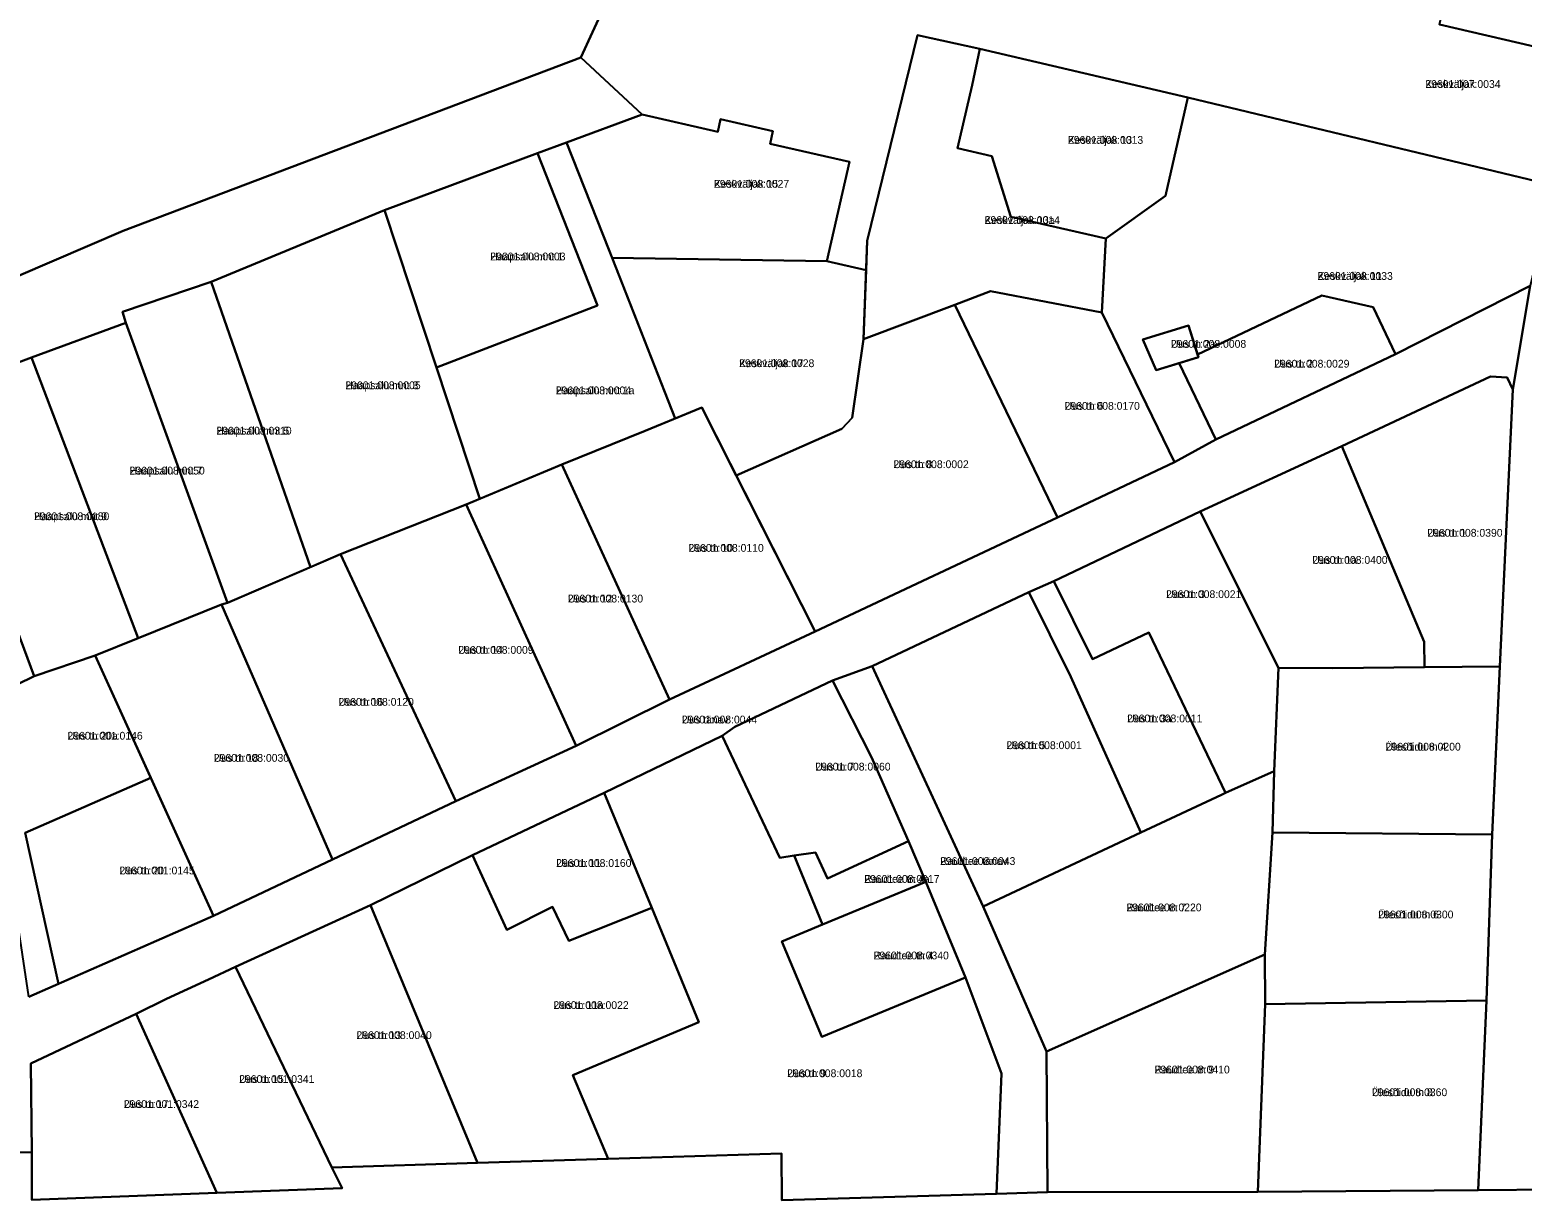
# Model space of a CAD drawing. Extents: x 518839 to 525192, y 6573164 to 6576561.
# Drawn here: x 523942.5 to 524230.2, y 6574325 to 6574550.6 of the extents above; entities that cross this region are included whole.
import ezdxf

# ---------------------------------------------------------------- set-up
doc = ezdxf.new("R2010")
doc.units = 0
for name, color, linetype in [('L_AADRESS', 7, 'Continuous'), ('PIIR', 7, 'Continuous'), ('TUNNUS', 7, 'Continuous')]:
    doc.layers.add(name, color=color, linetype=linetype)

msp = doc.modelspace()

# ---------------------------------------------------------------- linework, layer by layer
at = {"layer": 'PIIR'}
for points in [[(524261.43, 6574568.93), (524244.4, 6574544.59), (524214.28, 6574551.57), (524221.35, 6574582.67)], [(524113.63, 6574549.55), (524125.65, 6574546.87), (524124.21, 6574539.9), (524121.37, 6574527.77), (524127.96, 6574526.22), (524131.65, 6574514.49), (524149.94, 6574510.31), (524149.18, 6574496.1), (524127.7, 6574500.17), (524120.82, 6574497.56), (524103.22, 6574490.94), (524103.93, 6574509.88)], [(524125.65, 6574546.87), (524165.75, 6574537.51), (524161.44, 6574518.56), (524149.94, 6574510.31), (524131.65, 6574514.49), (524127.96, 6574526.22), (524121.37, 6574527.77), (524124.21, 6574539.9)], [(524165.75, 6574537.51), (524236.37, 6574520.54), (524231.72, 6574501.21), (524205.78, 6574488.03), (524201.49, 6574497.08), (524191.56, 6574499.32), (524167.64, 6574487.97), (524165.87, 6574493.59), (524157.06, 6574490.89), (524159.65, 6574484.94), (524164.05, 6574486.32), (524171.13, 6574471.57), (524163.19, 6574467.21), (524149.18, 6574496.1), (524149.94, 6574510.31), (524161.44, 6574518.56)], [(524046.01, 6574528.85), (524060.59, 6574534.25), (524075.12, 6574530.92), (524075.68, 6574533.35), (524085.77, 6574531.04), (524085.21, 6574528.6), (524100.5, 6574525.1), (524096.14, 6574505.98), (524054.77, 6574506.58), (524054.13, 6574508.2)], [(524046.01, 6574528.85), (524054.13, 6574508.2), (524066.94, 6574475.63), (524061.16, 6574473.29), (524045.1, 6574466.79), (524029.26, 6574460.17), (524020.9, 6574485.49), (524051.93, 6574497.39), (524040.38, 6574526.76)], [(524040.38, 6574526.76), (524051.93, 6574497.39), (524020.9, 6574485.49), (524010.89, 6574515.83)], [(524010.89, 6574515.83), (524020.9, 6574485.49), (524029.26, 6574460.17), (524026.62, 6574459.07), (524002.42, 6574449.49), (523996.62, 6574446.97), (523977.46, 6574501.97)], [(524054.77, 6574506.58), (524096.14, 6574505.98), (524103.72, 6574504.25), (524103.22, 6574490.94), (524101.04, 6574475.74), (524099.06, 6574473.65), (524078.71, 6574464.62), (524072.05, 6574477.78), (524066.94, 6574475.63)], [(523996.62, 6574446.97), (523980.65, 6574440.13), (523961.02, 6574494.08), (523960.36, 6574496.17), (523977.46, 6574501.97)], [(524127.7, 6574500.17), (524149.18, 6574496.1), (524163.19, 6574467.21), (524140.64, 6574456.54), (524120.82, 6574497.56)], [(524140.64, 6574456.54), (524093.9, 6574434.59), (524078.71, 6574464.62), (524099.06, 6574473.65), (524101.04, 6574475.74), (524103.22, 6574490.94), (524120.82, 6574497.56)], [(524164.05, 6574486.32), (524167.79, 6574487.49), (524167.64, 6574487.97), (524191.56, 6574499.32), (524201.49, 6574497.08), (524205.78, 6574488.03), (524171.13, 6574471.57)], [(523963.4, 6574433.26), (523942.85, 6574487.39), (523961.02, 6574494.08), (523980.65, 6574440.13), (523979.48, 6574439.76)], [(524167.79, 6574487.49), (524159.65, 6574484.94), (524157.06, 6574490.89), (524165.87, 6574493.59)], [(523923.27, 6574480.06), (523942.85, 6574487.39), (523963.4, 6574433.26), (523955.11, 6574429.92), (523943.34, 6574425.96)], [(524224.11, 6574483.71), (524227.33, 6574483.53), (524228.42, 6574481.2), (524225.88, 6574427.83), (524211.35, 6574427.68), (524211.3, 6574432.57), (524195.42, 6574470.32)], [(523923.27, 6574480.06), (523943.34, 6574425.96), (523933.73, 6574421.28), (523927.24, 6574420.14), (523906.23, 6574473.68)], [(524045.1, 6574466.79), (524061.16, 6574473.29), (524072.05, 6574477.78), (524093.9, 6574434.59), (524065.86, 6574421.45)], [(524211.3, 6574432.57), (524211.35, 6574427.68), (524193.71, 6574427.5), (524183.2, 6574427.59), (524168.15, 6574457.71), (524195.42, 6574470.32)], [(524045.1, 6574466.79), (524065.86, 6574421.45), (524047.84, 6574412.54), (524026.62, 6574459.07)], [(524026.62, 6574459.07), (524047.84, 6574412.54), (524024.62, 6574401.85), (524002.42, 6574449.49)], [(524139.92, 6574444.3), (524168.15, 6574457.71), (524183.2, 6574427.59), (524182.42, 6574407.66), (524173.02, 6574403.45), (524158.24, 6574434.41), (524147.4, 6574429.26)], [(523979.48, 6574439.76), (523980.65, 6574440.13), (524002.42, 6574449.49), (524024.62, 6574401.85), (524000.89, 6574390.65)], [(524104.91, 6574427.9), (524135.07, 6574442.17), (524143.18, 6574425.84), (524156.7, 6574395.81), (524126.31, 6574381.54)], [(524135.07, 6574442.17), (524139.92, 6574444.3), (524147.4, 6574429.26), (524158.24, 6574434.41), (524173.02, 6574403.45), (524172.27, 6574403.11), (524156.7, 6574395.81), (524143.18, 6574425.84)], [(523955.11, 6574429.92), (523963.4, 6574433.26), (523979.48, 6574439.76), (524000.89, 6574390.65), (523977.96, 6574379.73)], [(523942.36, 6574364.13), (523933.73, 6574421.28), (523943.34, 6574425.96), (523955.11, 6574429.92), (523965.83, 6574406.37), (523941.65, 6574395.76), (523948.05, 6574366.62)], [(524097.28, 6574425.15), (524104.91, 6574427.9), (524126.31, 6574381.54), (524138.49, 6574353.61), (524138.73, 6574326.48), (524128.88, 6574326.17), (524129.82, 6574349.36), (524122.87, 6574367.85), (524115.23, 6574386.33), (524111.93, 6574394.17), (524104.76, 6574410.33)], [(524182.42, 6574407.66), (524183.2, 6574427.59), (524193.71, 6574427.5), (524211.35, 6574427.68), (524225.88, 6574427.83), (524224.41, 6574395.41), (524182.05, 6574395.81)], [(524078.45, 6574416.17), (524097.28, 6574425.15), (524104.76, 6574410.33), (524111.93, 6574394.17), (524096.32, 6574386.94), (524094, 6574391.99), (524089.86, 6574391.37), (524087.08, 6574390.92), (524075.96, 6574414.43)], [(524062.4, 6574381.3), (524053.25, 6574403.45), (524075.96, 6574414.43), (524087.08, 6574390.92), (524089.86, 6574391.37), (524095.33, 6574378.08), (524087.48, 6574374.84), (524095.21, 6574356.41), (524122.87, 6574367.85), (524129.82, 6574349.36), (524128.88, 6574326.17), (524087.52, 6574324.95), (524087.42, 6574333.93), (524053.99, 6574332.93), (524047.23, 6574349.06), (524071.46, 6574359.29)], [(524138.49, 6574353.61), (524126.31, 6574381.54), (524156.7, 6574395.81), (524172.27, 6574403.11), (524173.02, 6574403.45), (524182.42, 6574407.66), (524182.05, 6574395.81), (524180.58, 6574372.29)], [(523948.05, 6574366.62), (523941.65, 6574395.76), (523965.83, 6574406.37), (523977.96, 6574379.73)], [(524053.25, 6574403.45), (524062.4, 6574381.3), (524046.41, 6574374.93), (524043.25, 6574381.47), (524034.5, 6574377.05), (524027.83, 6574391.43)], [(524223.35, 6574363.46), (524180.64, 6574362.74), (524180.58, 6574372.29), (524182.05, 6574395.81), (524224.41, 6574395.41)], [(524089.86, 6574391.37), (524094, 6574391.99), (524096.32, 6574386.94), (524111.93, 6574394.17), (524115.23, 6574386.33), (524095.33, 6574378.08)], [(524008.18, 6574381.82), (524027.83, 6574391.43), (524034.5, 6574377.05), (524043.25, 6574381.47), (524046.41, 6574374.93), (524062.4, 6574381.3), (524071.46, 6574359.29), (524047.23, 6574349.06), (524053.99, 6574332.93), (524028.8, 6574332.17)], [(524122.87, 6574367.85), (524095.21, 6574356.41), (524087.48, 6574374.84), (524095.33, 6574378.08), (524115.23, 6574386.33)], [(523982.2, 6574369.96), (524008.18, 6574381.82), (524028.8, 6574332.17), (524000.72, 6574331.27)], [(523978.59, 6574326.39), (523963.04, 6574360.87), (523968.9, 6574363.77), (523976.95, 6574367.51), (523982.2, 6574369.96), (524000.72, 6574331.27), (524002.73, 6574327.27)], [(524138.49, 6574353.61), (524180.58, 6574372.29), (524180.64, 6574362.74), (524179.26, 6574326.53), (524138.73, 6574326.48)], [(524179.26, 6574326.53), (524180.64, 6574362.74), (524223.35, 6574363.46), (524221.73, 6574326.86)], [(523942.7, 6574351.27), (523963.04, 6574360.87), (523978.59, 6574326.39), (523942.94, 6574325.03), (523942.9, 6574334.18)]]:
    msp.add_lwpolyline(points, close=True, dxfattribs=at)
for points in [[(524055.5, 6574559.93), (524048.74, 6574545.24), (523960.55, 6574511.82), (523926.54, 6574497.21), (523925.89, 6574498.49), (523851.65, 6574467.07), (523749.34, 6574437.4), (523743.19, 6574435.09), (523741.03, 6574444.43), (523755.4, 6574447.87), (523750.58, 6574460.99), (523737.98, 6574458.09), (523730.41, 6574491.16), (523715.18, 6574570.22)], [(524236.37, 6574520.54), (524165.75, 6574537.51), (524125.65, 6574546.87), (524113.63, 6574549.55), (524103.93, 6574509.88), (524103.72, 6574504.25), (524096.14, 6574505.98), (524100.5, 6574525.1), (524085.21, 6574528.6), (524085.77, 6574531.04), (524075.68, 6574533.35), (524075.12, 6574530.92), (524060.59, 6574534.25), (524048.74, 6574545.24), (524055.5, 6574559.93)], [(524214.28, 6574551.57), (524244.4, 6574544.59)], [(523926.54, 6574497.21), (523960.55, 6574511.82), (524048.74, 6574545.24), (524060.59, 6574534.25), (524046.01, 6574528.85), (524040.38, 6574526.76), (524010.89, 6574515.83), (523977.46, 6574501.97), (523960.36, 6574496.17), (523961.02, 6574494.08), (523942.85, 6574487.39), (523923.27, 6574480.06)], [(523942.36, 6574364.13), (523977.96, 6574379.73), (524000.89, 6574390.65), (524024.62, 6574401.85), (524047.84, 6574412.54), (524065.86, 6574421.45), (524093.9, 6574434.59), (524140.64, 6574456.54), (524163.19, 6574467.21), (524171.13, 6574471.57), (524205.78, 6574488.03), (524231.72, 6574501.21), (524228.42, 6574481.2), (524227.33, 6574483.53), (524224.11, 6574483.71), (524195.42, 6574470.32), (524168.15, 6574457.71), (524139.92, 6574444.3), (524135.07, 6574442.17), (524104.91, 6574427.9), (524097.28, 6574425.15), (524078.45, 6574416.17), (524075.96, 6574414.43), (524053.25, 6574403.45), (524027.83, 6574391.43), (524008.18, 6574381.82), (523982.2, 6574369.96), (523976.95, 6574367.51), (523968.9, 6574363.77), (523963.04, 6574360.87), (523942.7, 6574351.27), (523942.9, 6574334.18), (523926.86, 6574333.79)], [(524236.58, 6574327.02), (524221.73, 6574326.86), (524223.35, 6574363.46), (524224.41, 6574395.41), (524225.88, 6574427.83), (524228.42, 6574481.2), (524231.72, 6574501.21)], [(523926.86, 6574333.79), (523942.9, 6574334.18), (523942.94, 6574325.03), (523978.59, 6574326.39), (524002.73, 6574327.27), (524000.72, 6574331.27), (524028.8, 6574332.17), (524053.99, 6574332.93), (524087.42, 6574333.93), (524087.52, 6574324.95), (524128.88, 6574326.17), (524138.73, 6574326.48), (524179.26, 6574326.53), (524221.73, 6574326.86), (524236.58, 6574327.02)]]:
    msp.add_lwpolyline(points, dxfattribs=at)

# ---------------------------------------------------------------- texts
at = {"layer": 'L_AADRESS'}
for s, p in [('Keskväljak', (524211.53, 6574539.36)), ('Keskväljak 13', (524142.64, 6574528.59)), ('Keskväljak 15', (524074.4, 6574520.12)), ('Keskväljak 13a', (524126.58, 6574513.14)), ('Haapsalu mnt 1', (524031.29, 6574506.12)), ('Keskväljak 11', (524190.76, 6574502.36)), ('Uus tn 2a', (524162.5, 6574489.27)), ('Keskväljak 17', (524079.25, 6574485.54)), ('Uus tn 2', (524182.4, 6574485.45)), ('Haapsalu mnt 3', (524003.36, 6574481.29)), ('Haapsalu mnt 1a', (524043.92, 6574480.31)), ('Uus tn 6', (524142, 6574477.32)), ('Haapsalu mnt 5', (523978.49, 6574472.54)), ('Haapsalu mnt 7', (523961.75, 6574464.84)), ('Uus tn 8', (524109.01, 6574466.07)), ('Haapsalu mnt 9', (523943.34, 6574456.04)), ('Uus tn 1', (524211.92, 6574452.85)), ('Uus tn 10', (524069.5, 6574449.94)), ('Uus tn 1a', (524189.75, 6574447.62)), ('Uus tn 3', (524161.56, 6574441.02)), ('Uus tn 12', (524046.24, 6574440.17)), ('Uus tn 14', (524025.13, 6574430.28)), ('Uus tn 16', (524002.05, 6574420.26)), ('Uus tänav', (524068.22, 6574416.85)), ('Uus tn 3a', (524154.05, 6574417.06)), ('Uus tn 20a', (523949.78, 6574413.73)), ('Uus tn 5', (524130.8, 6574411.9)), ('Ülesõidu tn 4', (524203.86, 6574411.62)), ('Uus tn 18', (523978, 6574409.46)), ('Uus tn 7', (524093.95, 6574407.77)), ('Uus tn 11', (524044, 6574389.19)), ('Raudtee tänav', (524118, 6574389.57)), ('Uus tn 20', (523959.8, 6574387.75)), ('Raudtee tn 4a', (524103.38, 6574386.12)), ('Raudtee tn 7', (524153.9, 6574380.63)), ('Ülesõidu tn 6', (524202.45, 6574379.27)), ('Raudtee tn 4', (524105.18, 6574371.37)), ('Uus tn 11a', (524043.46, 6574361.8)), ('Uus tn 13', (524005.5, 6574356.01)), ('Uus tn 9', (524088.52, 6574348.66)), ('Raudtee tn 9', (524159.33, 6574349.38)), ('Uus tn 15', (523982.88, 6574347.54)), ('Uus tn 17', (523960.65, 6574342.72)), ('Ülesõidu tn 8', (524201.25, 6574345))]:
    msp.add_text(s, height=1.5, dxfattribs=at).set_placement(p)
at = {"layer": 'TUNNUS'}
for s, p in [('29601:007:0034', (524211.53, 6574539.36)), ('29601:008:0013', (524142.64, 6574528.59)), ('29601:008:0027', (524074.4, 6574520.12)), ('29601:008:0014', (524126.58, 6574513.14)), ('29601:008:0003', (524031.29, 6574506.12)), ('29601:008:0033', (524190.76, 6574502.36)), ('29601:008:0008', (524162.5, 6574489.27)), ('29601:008:0028', (524079.25, 6574485.54)), ('29601:008:0029', (524182.4, 6574485.45)), ('29601:008:0005', (524003.36, 6574481.29)), ('29601:008:0004', (524043.92, 6574480.31)), ('29601:008:0170', (524142, 6574477.32)), ('29601:008:0310', (523978.49, 6574472.54)), ('29601:008:0050', (523961.75, 6574464.84)), ('29601:008:0002', (524109.01, 6574466.07)), ('29601:008:0180', (523943.34, 6574456.04)), ('29601:008:0390', (524211.92, 6574452.85)), ('29601:008:0110', (524069.5, 6574449.94)), ('29601:008:0400', (524189.75, 6574447.62)), ('29601:008:0021', (524161.56, 6574441.02)), ('29601:008:0130', (524046.24, 6574440.17)), ('29601:008:0009', (524025.13, 6574430.28)), ('29601:008:0120', (524002.05, 6574420.26)), ('29601:008:0044', (524068.22, 6574416.85)), ('29601:008:0011', (524154.05, 6574417.06)), ('29601:001:0146', (523949.78, 6574413.73)), ('29601:008:0001', (524130.8, 6574411.9)), ('29601:008:0200', (524203.86, 6574411.62)), ('29601:008:0030', (523978, 6574409.46)), ('29601:008:0060', (524093.95, 6574407.77)), ('29601:008:0160', (524044, 6574389.19)), ('29601:008:0043', (524118, 6574389.57)), ('29601:001:0145', (523959.8, 6574387.75)), ('29601:008:0017', (524103.38, 6574386.12)), ('29601:008:0220', (524153.9, 6574380.63)), ('29601:008:0300', (524202.45, 6574379.27)), ('29601:008:0340', (524105.18, 6574371.37)), ('29601:008:0022', (524043.46, 6574361.8)), ('29601:008:0040', (524005.5, 6574356.01)), ('29601:008:0018', (524088.52, 6574348.66)), ('29601:008:0410', (524159.33, 6574349.38)), ('29601:001:0341', (523982.88, 6574347.54)), ('29601:001:0342', (523960.65, 6574342.72)), ('29601:008:0360', (524201.25, 6574345))]:
    msp.add_text(s, height=1.5, dxfattribs=at).set_placement(p)

doc.saveas('drawing.dxf')
